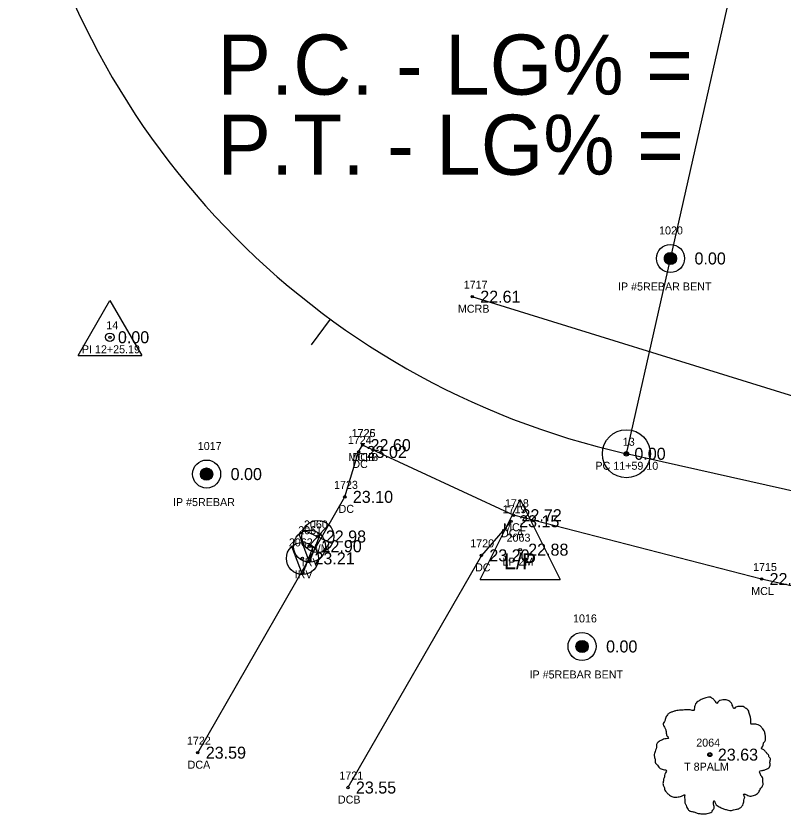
# Model space of a CAD drawing. Extents: x 2654414 to 2656963, y 761776 to 764965.
# Drawn here: x 2655244.9 to 2655340.6, y 762185.2 to 762284.8 of the extents above; entities that cross this region are included whole.
import ezdxf

# ---------------------------------------------------------------- set-up
doc = ezdxf.new("R2010")
doc.units = 0
for name, color, linetype in [('RD_EX_BldgApp', 7, 'Continuous'), ('RD_EX_Conc', 7, 'Continuous'), ('RD_EX_Conc_txCode', 7, 'Continuous'), ('RD_EX_DV_Prop_txCode', 7, 'Continuous'), ('RD_EX_DV_PropPin', 7, 'Continuous'), ('RD_EX_Misc_txCode', 7, 'Continuous'), ('RD_EX_TX_Conc_ELEV', 7, 'Continuous'), ('RD_EX_TX_DV_Prop_ELEV', 7, 'Continuous'), ('RD_EX_TX_Misc_ELEV', 7, 'Continuous'), ('RD_EX_TX_UT_ELEV', 7, 'Continuous'), ('RD_EX_TX_VEG_ELEV', 7, 'Continuous'), ('RD_EX_UT', 7, 'Continuous'), ('RD_EX_UT_txCode', 7, 'Continuous'), ('RD_EX_VEG', 7, 'Continuous'), ('RD_EX_VEG_txCode', 7, 'Continuous'), ('RD_HC_Cl', 7, 'Continuous'), ('RD_HC_Data', 7, 'Continuous'), ('RD_HC_Data_Tic', 7, 'Continuous'), ('RD_HC_Survey_ELEV', 7, 'Continuous'), ('RD_HC_txCode', 7, 'Continuous'), ('RD_SMD_Locator', 7, 'Continuous')]:
    doc.layers.add(name, color=color, linetype=linetype)

msp = doc.modelspace()

# ---------------------------------------------------------------- linework, layer by layer
at = {"layer": 'RD_EX_BldgApp'}
for p, q in [((2655281.507, 762216.625), (2655280.203, 762220.108)), ((2655281.507, 762216.625), (2655282.829, 762220.071)), ((2655280.621, 762215.105), (2655279.317, 762218.587)), ((2655280.621, 762215.105), (2655281.943, 762218.55))]:
    msp.add_line(p, q, dxfattribs=at)
for centre, radius in [((2655281.507, 762218.618), 2), ((2655280.621, 762217.097), 2), ((2655281.507, 762218.618), 0.15), ((2655280.621, 762217.097), 0.15)]:
    msp.add_circle(centre, radius, dxfattribs=at)
at = {"layer": 'RD_EX_Conc'}
for points in [[(2655447.671, 762217.38), (2655447.327, 762216.453), (2655403.547, 762226.108), (2655380.017, 762230.002), (2655342.631, 762237.105), (2655301.817, 762249.774)], [(2655267.557, 762192.84), (2655285.913, 762224.783), (2655287.633, 762230.384), (2655288.125, 762231.245)], [(2655440.54, 762187.622), (2655439.059, 762188.617), (2655385.758, 762201.571), (2655364.155, 762208.612), (2655337.932, 762214.524), (2655306.963, 762222.49), (2655288.125, 762231.245)], [(2655306.669, 762221.736), (2655302.951, 762217.479), (2655286.297, 762188.489)]]:
    msp.add_lwpolyline(points, dxfattribs=at)
at = {"layer": 'RD_EX_DV_PropPin'}
for p, q in [((2655325.824, 762254.353), (2655325.824, 762254.745)), ((2655325.859, 762254.251), (2655325.859, 762254.847)), ((2655325.894, 762254.179), (2655325.894, 762254.919)), ((2655325.929, 762254.122), (2655325.929, 762254.976)), ((2655325.964, 762254.075), (2655325.964, 762255.023)), ((2655325.999, 762254.034), (2655325.999, 762255.064)), ((2655326.034, 762253.998), (2655326.034, 762255.1)), ((2655326.069, 762253.967), (2655326.069, 762255.131)), ((2655326.104, 762253.939), (2655326.104, 762255.159)), ((2655326.139, 762253.914), (2655326.139, 762255.184)), ((2655326.174, 762253.893), (2655326.174, 762255.205)), ((2655326.209, 762253.873), (2655326.209, 762255.225)), ((2655326.244, 762253.856), (2655326.244, 762255.242)), ((2655326.279, 762253.841), (2655326.279, 762255.257)), ((2655326.314, 762253.829), (2655326.314, 762255.269)), ((2655326.349, 762253.818), (2655326.349, 762255.28)), ((2655326.384, 762253.808), (2655326.384, 762255.29)), ((2655326.419, 762253.801), (2655326.419, 762255.297)), ((2655326.454, 762253.795), (2655326.454, 762255.303)), ((2655326.489, 762253.791), (2655326.489, 762255.307)), ((2655326.524, 762253.789), (2655326.524, 762255.309)), ((2655326.559, 762253.788), (2655326.559, 762255.31)), ((2655326.594, 762253.789), (2655326.594, 762255.309)), ((2655326.629, 762253.791), (2655326.629, 762255.307)), ((2655326.664, 762253.795), (2655326.664, 762255.303)), ((2655326.699, 762253.801), (2655326.699, 762255.297)), ((2655326.734, 762253.808), (2655326.734, 762255.29)), ((2655326.769, 762253.818), (2655326.769, 762255.28)), ((2655326.804, 762253.829), (2655326.804, 762255.269)), ((2655326.839, 762253.841), (2655326.839, 762255.257)), ((2655326.874, 762253.856), (2655326.874, 762255.242)), ((2655326.909, 762253.873), (2655326.909, 762255.225)), ((2655326.944, 762253.893), (2655326.944, 762255.205)), ((2655326.979, 762253.914), (2655326.979, 762255.184)), ((2655327.014, 762253.939), (2655327.014, 762255.159)), ((2655327.049, 762253.967), (2655327.049, 762255.131)), ((2655327.084, 762253.998), (2655327.084, 762255.1)), ((2655327.12, 762254.034), (2655327.12, 762255.064)), ((2655327.155, 762254.075), (2655327.155, 762255.023)), ((2655327.19, 762254.122), (2655327.19, 762254.976)), ((2655327.225, 762254.179), (2655327.225, 762254.919)), ((2655327.26, 762254.251), (2655327.26, 762254.847)), ((2655327.295, 762254.353), (2655327.295, 762254.745)), ((2655267.925, 762227.433), (2655267.925, 762227.825)), ((2655267.96, 762227.331), (2655267.96, 762227.927)), ((2655267.995, 762227.26), (2655267.995, 762227.999)), ((2655268.03, 762227.203), (2655268.03, 762228.056)), ((2655268.065, 762227.155), (2655268.065, 762228.103)), ((2655268.1, 762227.114), (2655268.1, 762228.144)), ((2655268.135, 762227.078), (2655268.135, 762228.18)), ((2655268.17, 762227.047), (2655268.17, 762228.211)), ((2655268.205, 762227.019), (2655268.205, 762228.239)), ((2655268.24, 762226.995), (2655268.24, 762228.264)), ((2655268.275, 762226.973), (2655268.275, 762228.285)), ((2655268.31, 762226.953), (2655268.31, 762228.305)), ((2655268.345, 762226.936), (2655268.345, 762228.322)), ((2655268.38, 762226.922), (2655268.38, 762228.337)), ((2655268.415, 762226.909), (2655268.415, 762228.35)), ((2655268.45, 762226.898), (2655268.45, 762228.361)), ((2655268.485, 762226.888), (2655268.485, 762228.37)), ((2655268.52, 762226.881), (2655268.52, 762228.377)), ((2655268.555, 762226.875), (2655268.555, 762228.383)), ((2655268.59, 762226.871), (2655268.59, 762228.387)), ((2655268.625, 762226.869), (2655268.625, 762228.389)), ((2655268.66, 762226.868), (2655268.66, 762228.39)), ((2655268.695, 762226.869), (2655268.695, 762228.389)), ((2655268.73, 762226.871), (2655268.73, 762228.387)), ((2655268.765, 762226.875), (2655268.765, 762228.383)), ((2655268.8, 762226.881), (2655268.8, 762228.377)), ((2655268.835, 762226.888), (2655268.835, 762228.37)), ((2655268.87, 762226.898), (2655268.87, 762228.361)), ((2655268.905, 762226.909), (2655268.905, 762228.35)), ((2655268.94, 762226.922), (2655268.94, 762228.337)), ((2655268.976, 762226.936), (2655268.976, 762228.322)), ((2655269.011, 762226.953), (2655269.011, 762228.305)), ((2655269.046, 762226.973), (2655269.046, 762228.285)), ((2655269.081, 762226.995), (2655269.081, 762228.264)), ((2655269.116, 762227.019), (2655269.116, 762228.239)), ((2655269.151, 762227.047), (2655269.151, 762228.211)), ((2655269.186, 762227.078), (2655269.186, 762228.18)), ((2655269.221, 762227.114), (2655269.221, 762228.144)), ((2655269.256, 762227.155), (2655269.256, 762228.103)), ((2655269.291, 762227.203), (2655269.291, 762228.056)), ((2655269.326, 762227.26), (2655269.326, 762227.999)), ((2655269.361, 762227.331), (2655269.361, 762227.927)), ((2655269.396, 762227.433), (2655269.396, 762227.825)), ((2655314.891, 762205.678), (2655314.891, 762206.531)), ((2655314.926, 762205.631), (2655314.926, 762206.579)), ((2655314.961, 762205.59), (2655314.961, 762206.62)), ((2655314.996, 762205.554), (2655314.996, 762206.656)), ((2655315.031, 762205.523), (2655315.031, 762206.687)), ((2655315.066, 762205.495), (2655315.066, 762206.715)), ((2655315.102, 762205.47), (2655315.102, 762206.739)), ((2655315.137, 762205.448), (2655315.137, 762206.761)), ((2655315.172, 762205.429), (2655315.172, 762206.78)), ((2655315.207, 762205.412), (2655315.207, 762206.798)), ((2655315.242, 762205.397), (2655315.242, 762206.812)), ((2655315.277, 762205.384), (2655315.277, 762206.825)), ((2655315.312, 762205.373), (2655315.312, 762206.836)), ((2655315.347, 762205.364), (2655315.347, 762206.845)), ((2655315.382, 762205.357), (2655315.382, 762206.853)), ((2655315.417, 762205.351), (2655315.417, 762206.859)), ((2655315.452, 762205.347), (2655315.452, 762206.863)), ((2655315.487, 762205.345), (2655315.487, 762206.865)), ((2655315.522, 762205.344), (2655315.522, 762206.866)), ((2655315.557, 762205.345), (2655315.557, 762206.865)), ((2655315.592, 762205.347), (2655315.592, 762206.863)), ((2655315.627, 762205.351), (2655315.627, 762206.859)), ((2655315.662, 762205.357), (2655315.662, 762206.853)), ((2655315.697, 762205.364), (2655315.697, 762206.845)), ((2655315.732, 762205.373), (2655315.732, 762206.836)), ((2655315.767, 762205.384), (2655315.767, 762206.825)), ((2655315.802, 762205.397), (2655315.802, 762206.812)), ((2655315.837, 762205.412), (2655315.837, 762206.798)), ((2655315.872, 762205.429), (2655315.872, 762206.78)), ((2655315.907, 762205.448), (2655315.907, 762206.761)), ((2655315.942, 762205.47), (2655315.942, 762206.739)), ((2655315.977, 762205.495), (2655315.977, 762206.715)), ((2655316.012, 762205.523), (2655316.012, 762206.687)), ((2655316.047, 762205.554), (2655316.047, 762206.656)), ((2655316.082, 762205.59), (2655316.082, 762206.62)), ((2655316.117, 762205.631), (2655316.117, 762206.579)), ((2655316.152, 762205.678), (2655316.152, 762206.531)), ((2655314.786, 762205.909), (2655314.786, 762206.301)), ((2655314.821, 762205.807), (2655314.821, 762206.403)), ((2655314.856, 762205.735), (2655314.856, 762206.474)), ((2655316.187, 762205.735), (2655316.187, 762206.474)), ((2655316.222, 762205.807), (2655316.222, 762206.403)), ((2655316.257, 762205.909), (2655316.257, 762206.301))]:
    msp.add_line(p, q, dxfattribs=at)
for centre, radius in [((2655326.559, 762254.549), 1.75), ((2655326.559, 762254.549), 0.761), ((2655268.66, 762227.629), 1.75), ((2655268.66, 762227.629), 0.761), ((2655315.522, 762206.105), 1.75), ((2655315.522, 762206.105), 0.761)]:
    msp.add_circle(centre, radius, dxfattribs=at)
at = {"layer": 'RD_EX_UT'}
for p, q in [((2655302.798, 762214.464), (2655307.798, 762224.464)), ((2655307.798, 762224.464), (2655312.798, 762214.464)), ((2655280.709, 762220.671), (2655284.34, 762218.958)), ((2655281.19, 762218.376), (2655283.858, 762221.272)), ((2655302.798, 762214.464), (2655312.798, 762214.464))]:
    msp.add_line(p, q, dxfattribs=at)
msp.add_circle((2655282.542, 762219.834), 2, dxfattribs=at)
at = {"layer": 'RD_EX_VEG'}
for centre, radius in [((2655331.469, 762192.595), 0.25), ((2655331.456, 762192.576), 0.0001)]:
    msp.add_circle(centre, radius, dxfattribs=at)
for points in [[(2655331.601, 762199.762), (2655331.301, 762199.787), (2655330.976, 762199.687), (2655330.726, 762199.587), (2655330.501, 762199.512), (2655330.277, 762199.412), (2655329.977, 762199.238), (2655329.752, 762199.038), (2655329.627, 762198.788), (2655329.577, 762198.563), (2655329.527, 762198.288), (2655329.527, 762198.113), (2655329.402, 762198.088), (2655329.252, 762198.113), (2655329.002, 762198.188), (2655328.752, 762198.188), (2655328.502, 762198.188), (2655328.152, 762198.163), (2655327.803, 762198.163), (2655327.528, 762198.113), (2655327.203, 762198.063), (2655326.828, 762197.938), (2655326.478, 762197.813), (2655326.178, 762197.563), (2655325.928, 762197.089), (2655325.803, 762196.739), (2655325.654, 762196.489), (2655325.803, 762196.039), (2655325.978, 762195.689), (2655326.003, 762195.489), (2655326.078, 762195.064), (2655326.178, 762194.84), (2655326.303, 762194.64), (2655326.228, 762194.615), (2655325.853, 762194.565), (2655325.554, 762194.465), (2655325.129, 762194.24), (2655324.904, 762194.015), (2655324.804, 762193.69), (2655324.779, 762193.34), (2655324.679, 762193.14), (2655324.604, 762192.865), (2655324.579, 762192.79), (2655324.529, 762192.466), (2655324.629, 762192.016), (2655324.654, 762191.666), (2655324.779, 762191.441), (2655324.929, 762191.266), (2655325.104, 762191.016), (2655325.504, 762190.791), (2655325.828, 762190.691), (2655326.028, 762190.666), (2655325.853, 762190.167), (2655325.803, 762189.817), (2655325.679, 762189.417), (2655325.679, 762189.342), (2655325.629, 762188.867), (2655325.778, 762188.542), (2655325.853, 762188.167), (2655326.028, 762187.943), (2655326.303, 762187.643), (2655326.628, 762187.418), (2655327.128, 762187.293), (2655327.528, 762187.318), (2655328.103, 762187.493), (2655328.352, 762187.568), (2655328.327, 762187.393), (2655328.352, 762187.018), (2655328.352, 762186.593), (2655328.502, 762186.268), (2655328.602, 762185.993), (2655328.752, 762185.743), (2655329.077, 762185.519), (2655329.477, 762185.444), (2655329.902, 762185.294), (2655330.352, 762185.219), (2655330.851, 762185.194), (2655331.451, 762185.344), (2655331.726, 762185.469), (2655331.826, 762185.644), (2655332.026, 762186.018), (2655331.976, 762186.243), (2655332.001, 762186.843), (2655332.101, 762186.668), (2655332.276, 762186.318), (2655332.775, 762186.018), (2655333.175, 762185.843), (2655333.65, 762185.693), (2655333.95, 762185.619), (2655334.425, 762185.693), (2655334.8, 762185.768), (2655335.174, 762185.893), (2655335.474, 762186.168), (2655335.649, 762186.443), (2655335.699, 762186.718), (2655335.774, 762187.093), (2655335.824, 762187.268)], [(2655335.824, 762187.268), (2655335.749, 762187.443), (2655335.699, 762187.693), (2655335.774, 762187.668), (2655335.949, 762187.618), (2655336.224, 762187.493), (2655336.449, 762187.418), (2655336.774, 762187.443), (2655337.049, 762187.543), (2655337.498, 762187.818), (2655337.773, 762188.292), (2655338.048, 762188.692), (2655338.123, 762189.017), (2655338.073, 762189.242), (2655338.048, 762189.742), (2655337.848, 762189.992), (2655337.798, 762190.117), (2655337.698, 762190.516), (2655337.773, 762190.566), (2655338.048, 762190.616), (2655338.423, 762190.741), (2655338.698, 762190.866), (2655338.923, 762191.041), (2655338.998, 762191.266), (2655338.973, 762191.666), (2655339.023, 762192.066), (2655338.948, 762192.216), (2655338.848, 762192.366), (2655338.773, 762192.566), (2655338.623, 762192.715), (2655338.523, 762192.865), (2655338.423, 762192.965), (2655338.298, 762193.115), (2655338.123, 762193.24), (2655337.973, 762193.29), (2655337.923, 762193.44), (2655338.073, 762193.64), (2655338.123, 762193.74), (2655338.148, 762193.965), (2655338.373, 762194.315), (2655338.423, 762194.715), (2655338.373, 762195.139), (2655338.323, 762195.414), (2655338.173, 762195.689), (2655337.973, 762195.939), (2655337.848, 762196.114), (2655337.673, 762196.239), (2655337.348, 762196.364), (2655337.099, 762196.414), (2655336.749, 762196.414), (2655336.549, 762196.464), (2655336.574, 762196.514), (2655336.574, 762196.664), (2655336.574, 762196.939), (2655336.499, 762197.388), (2655336.349, 762197.888), (2655336.349, 762197.913), (2655336.249, 762198.163), (2655336.024, 762198.363), (2655335.849, 762198.463), (2655335.649, 762198.588), (2655335.399, 762198.613), (2655335.099, 762198.613), (2655334.825, 762198.563), (2655334.625, 762198.463), (2655334.45, 762198.338), (2655334.375, 762198.488), (2655334.275, 762198.788), (2655334.225, 762198.938), (2655334.075, 762199.113), (2655333.85, 762199.313), (2655333.4, 762199.437), (2655332.775, 762199.363), (2655332.476, 762199.163), (2655332.326, 762198.988), (2655332.276, 762199.113), (2655332.076, 762199.313), (2655331.976, 762199.487), (2655331.801, 762199.612), (2655331.651, 762199.712), (2655331.551, 762199.762)]]:
    msp.add_spline(points, degree=3, dxfattribs=at)
at = {"layer": 'RD_HC_Cl'}
msp.add_line((2655476.255, 762195.138), (2655321.054, 762230.163), dxfattribs=at)
msp.add_arc((2655343.007, 762327.438), 99.722, 190.21788, 257.28301, dxfattribs=at)
at = {"layer": 'RD_HC_Data'}
for p, q in [((2655321.054, 762230.163), (2655346.742, 762343.99)), ((2655252.619, 762242.418), (2655256.591, 762249.297)), ((2655256.591, 762249.297), (2655260.56, 762242.418)), ((2655252.619, 762242.418), (2655260.56, 762242.418))]:
    msp.add_line(p, q, dxfattribs=at)
for centre, radius in [((2655256.59, 762244.71), 0.529), ((2655321.054, 762230.163), 3), ((2655321.054, 762230.163), 0.282)]:
    msp.add_circle(centre, radius, dxfattribs=at)
at = {"layer": 'RD_HC_Data_Tic'}
msp.add_line((2655284.091, 762246.981), (2655281.727, 762243.754), dxfattribs=at)
at = {"layer": 'RD_SMD_Locator'}
for centre in [(2655326.559, 762254.549), (2655301.817, 762249.774), (2655256.59, 762244.71), (2655287.633, 762230.384), (2655288.125, 762231.245), (2655288.125, 762231.245), (2655321.054, 762230.163), (2655268.66, 762227.629), (2655285.913, 762224.783), (2655306.963, 762222.49), (2655306.669, 762221.736), (2655282.542, 762219.834), (2655302.951, 762217.479), (2655307.798, 762218.189), (2655337.932, 762214.524), (2655315.522, 762206.105), (2655267.557, 762192.84), (2655331.469, 762192.595), (2655286.297, 762188.489)]:
    msp.add_circle(centre, 0.15, dxfattribs=at)

# ---------------------------------------------------------------- texts
at = {"layer": 'RD_EX_Conc_txCode'}
for s, p in [('1717', (2655300.754, 762250.774)), ('MCRB', (2655300.029, 762247.774)), ('1726', (2655286.754, 762232.245)), ('1725', (2655286.778, 762232.245)), ('1724', (2655286.286, 762231.384)), ('MCLB', (2655286.361, 762229.245)), ('DCB', (2655286.873, 762229.245)), ('DC', (2655286.853, 762228.384)), ('1723', (2655284.567, 762225.783)), ('1718', (2655305.9, 762223.49)), ('DC', (2655285.134, 762222.783)), ('1719', (2655305.606, 762222.736)), ('MCL', (2655305.672, 762220.49)), ('DCA', (2655305.401, 762219.736)), ('1720', (2655301.565, 762218.479)), ('DC', (2655302.171, 762215.479)), ('1715', (2655336.869, 762215.524)), ('MCL', (2655336.64, 762212.524)), ('1722', (2655266.211, 762193.84)), ('DCA', (2655266.289, 762190.84)), ('1721', (2655285.234, 762189.489)), ('DCB', (2655285.045, 762186.489))]:
    msp.add_text(s, height=1, dxfattribs=at).set_placement(p)
at = {"layer": 'RD_EX_DV_Prop_txCode'}
for s, p in [('1020', (2655325.134, 762257.549)), ('IP #5REBAR BENT', (2655320.008, 762250.549)), ('1017', (2655267.558, 762230.629)), ('IP #5REBAR', (2655264.464, 762223.629)), ('1016', (2655314.396, 762209.105)), ('IP #5REBAR BENT', (2655308.971, 762202.105))]:
    msp.add_text(s, height=1, dxfattribs=at).set_placement(p)
at = {"layer": 'RD_EX_Misc_txCode'}
for s, p in [('2061', (2655280.097, 762220.118)), ('2062', (2655278.928, 762218.597)), ('IRV', (2655280.546, 762216.118)), ('IRV', (2655279.66, 762214.597))]:
    msp.add_text(s, height=1, dxfattribs=at).set_placement(p)
at = {"layer": 'RD_EX_TX_Conc_ELEV'}
for s, p in [('22.61', (2655302.817, 762249.024)), ('22.60', (2655289.125, 762230.495)), ('22.60', (2655289.125, 762230.495)), ('23.02', (2655288.633, 762229.634)), ('23.10', (2655286.913, 762224.033)), ('23.15', (2655307.669, 762220.986)), ('22.72', (2655307.963, 762221.74)), ('23.20', (2655303.951, 762216.729)), ('22.98', (2655338.932, 762213.774)), ('23.59', (2655268.557, 762192.09)), ('23.55', (2655287.297, 762187.739))]:
    msp.add_text(s, height=1.5, dxfattribs=at).set_placement(p)
at = {"layer": 'RD_EX_TX_DV_Prop_ELEV'}
for p in [(2655329.559, 762253.799), (2655271.66, 762226.879), (2655318.522, 762205.355)]:
    msp.add_text('0.00', height=1.5, dxfattribs=at).set_placement(p)
at = {"layer": 'RD_EX_TX_Misc_ELEV'}
for s, p in [('22.90', (2655283.007, 762217.868)), ('23.21', (2655282.121, 762216.347))]:
    msp.add_text(s, height=1.5, dxfattribs=at).set_placement(p)
at = {"layer": 'RD_EX_TX_UT_ELEV'}
for s, p in [('22.98', (2655283.542, 762219.084)), ('22.88', (2655308.798, 762217.439))]:
    msp.add_text(s, height=1.5, dxfattribs=at).set_placement(p)
at = {"layer": 'RD_EX_TX_VEG_ELEV'}
msp.add_text('23.63', height=1.5, dxfattribs=at).set_placement((2655332.469, 762191.845))
at = {"layer": 'RD_EX_UT'}
msp.add_text('L/P', height=2, dxfattribs=at).set_placement((2655305.789, 762215.746))
at = {"layer": 'RD_EX_UT_txCode'}
for s, p in [('2060', (2655280.81, 762220.834)), ('2063', (2655306.105, 762219.189)), ('WM', (2655281.637, 762217.834)), ('LP 2M', (2655305.585, 762216.189))]:
    msp.add_text(s, height=1, dxfattribs=at).set_placement(p)
at = {"layer": 'RD_EX_VEG_txCode'}
for s, p in [('2064', (2655329.776, 762193.595)), ('T 8PALM', (2655328.264, 762190.595))]:
    msp.add_text(s, height=1, dxfattribs=at).set_placement(p)
at = {"layer": 'RD_HC_Data'}
for s, p in [('P.C. - LG% = ', (2655270, 762275)), ('P.T. - LG% = ', (2655270, 762265))]:
    msp.add_text(s, height=7.5, dxfattribs=at).set_placement(p)
at = {"layer": 'RD_HC_Survey_ELEV'}
for p in [(2655257.59, 762243.96), (2655322.054, 762229.413)]:
    msp.add_text('0.00', height=1.5, dxfattribs=at).set_placement(p)
at = {"layer": 'RD_HC_txCode'}
for s, p in [('14', (2655256.141, 762245.71)), ('PI 12+25.19', (2655253.094, 762242.71)), ('13', (2655320.606, 762231.163)), ('PC 11+59.10', (2655317.188, 762228.163))]:
    msp.add_text(s, height=1, dxfattribs=at).set_placement(p)

doc.saveas('drawing.dxf')
